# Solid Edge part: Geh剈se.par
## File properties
Username: bmolnar
Dokumentum tartalom típus: 0
Author: bmolnar
Last saved by: bmolnar
Revision: 85
Sűrűség: 0,000 kg/m^3
Pontosság: 0,990
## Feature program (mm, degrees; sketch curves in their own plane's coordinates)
base feature "unnamed BaseFeature 1"
sketch for "unnamed Protrusion 1" plane through (-60, 17.5607, 34.5) normal (-1, 0, 0) x-axis (0, 0, 1)
  circle centre (178.5, 0.4393) radius 5
extrude "unnamed Protrusion 1" add finite 0.6 along +normal
chamfer "Letörés_1" setback 0.5  SetBackValue2 = 45 deg
sketch for "Kivágás_1" plane through (-60.6, 18, 35.2406) normal (-1, 0, 0) x-axis (0, 0, 1)
  line (174.8726, 0) -> (176.316, -2.5)
  line (176.316, -2.5) -> (179.2028, -2.5)
  line (179.2028, -2.5) -> (180.6461, 0)
  line (180.6461, 0) -> (179.2028, 2.5)
  line (179.2028, 2.5) -> (176.316, 2.5)
  line (176.316, 2.5) -> (174.8726, 0)
extrude "Kivágás_1" cut finite 4 along -normal
sketch for "Furat_1" plane through (-35.4, 27, 34.5) normal (0, 1, 0) x-axis (0, 0, 1)
  hole centre (-19.5, -4.1) bore radius 4.283
hole "Furat_1" nominal diameter 9.728 finite  ThreadDepth = 6 mm; StartChamferOffset = 0.7 mm; StartChamferAngle = 45 deg
sketch for "unnamed Hole 1" plane through (-35.4, 27, 34.5) normal (0, 1, 0) x-axis (0, 0, 1)
  hole centre (197.5, -4.1) bore radius 4.283
hole "unnamed Hole 1" finite
sketch for "Furat_3" plane through (-35.4, 27, 34.5) normal (0, 1, 0) x-axis (0, 0, 1)
  hole centre (-12.5, 10.4) bore radius 3.25
hole "Furat_3" diameter 6.5 finite  CounterBoreDepth = 7.5 mm
sketch for "unnamed Hole 2" plane through (-35.4, 27, 34.5) normal (0, 1, 0) x-axis (0, 0, 1)
  hole centre (111.5, 10.4) bore radius 3.25
hole "unnamed Hole 2" finite
sketch for "unnamed Hole 3" plane through (-35.4, 27, 34.5) normal (0, 1, 0) x-axis (0, 0, 1)
  hole centre (111.5, 60.4) bore radius 3.25
hole "unnamed Hole 3" finite
sketch for "unnamed Hole 4" plane through (-35.4, 27, 34.5) normal (0, 1, 0) x-axis (0, 0, 1)
  hole centre (-12.5, 60.4) bore radius 3.25
hole "unnamed Hole 4" finite
sketch for "Furat_7" plane through (25, -11, 22) normal (0, 1, 0) x-axis (0, 0, 1)
  hole centre (0, 0) bore radius 3.3235
hole "Furat_7" nominal diameter 8 finite  ThreadDepth = 16 mm
sketch for "unnamed Hole 5" plane through (25, -11, 22) normal (0, 1, 0) x-axis (0, 0, 1)
  hole centre (124, 0) bore radius 3.3235
hole "unnamed Hole 5" finite
sketch for "unnamed Hole 6" plane through (25, -11, 22) normal (0, 1, 0) x-axis (0, 0, 1)
  hole centre (124, -50) bore radius 3.3235
hole "unnamed Hole 6" finite
sketch for "unnamed Hole 7" plane through (25, -11, 22) normal (0, 1, 0) x-axis (0, 0, 1)
  hole centre (0, -50) bore radius 3.3235
hole "unnamed Hole 7" finite
sketch for "Furat_11" plane through (22.025, -27, 34.5) normal (0, -1, 0) x-axis (0, 0, 1)
  hole centre (49.5, -2.975) bore radius 2
hole "Furat_11" diameter 4 finite  CounterBoreDepth = 3 mm; VBottomAngle = 118 deg
sketch for "Furat_12" plane through (-22.025, -27, 34.5) normal (0, -1, 0) x-axis (0, 0, 1)
  hole centre (49.5, 2.975) bore radius 2
hole "Furat_12" diameter 4 finite  VBottomAngle = 118 deg
sketch for "Furat_13" plane through (0, 0, 244) normal (0, 0, 1) x-axis (-1, 0, 0)
  hole centre (-53, -20) bore radius 3.3235
hole "Furat_13" nominal diameter 8 finite  VBottomAngle = 118 deg; ThreadDepth = 16 mm; StartChamferOffset = 0.7 mm; StartChamferAngle = 45 deg
sketch for "unnamed Hole 8" plane through (0, 0, 244) normal (0, 0, 1) x-axis (-1, 0, 0)
  hole centre (-53, 20) bore radius 3.3235
hole "unnamed Hole 8" finite
sketch for "unnamed Hole 9" plane through (0, 0, 244) normal (0, 0, 1) x-axis (-1, 0, 0)
  hole centre (53, 19) bore radius 3.3235
hole "unnamed Hole 9" finite
sketch for "unnamed Hole 10" plane through (0, 0, 244) normal (0, 0, 1) x-axis (-1, 0, 0)
  hole centre (53, -20) bore radius 3.3235
hole "unnamed Hole 10" finite
pattern "unnamed Pattern 1" of "Furat_13", "unnamed Hole 8", "unnamed Hole 9", "unnamed Hole 10"
sketch for "Furat_19" plane through (0, 0, 244) normal (0, 0, 1) x-axis (1, 0, 0)
  hole centre (25, 0) bore radius 2
hole "Furat_19" diameter 4 finite  CounterBoreDepth = 3 mm; VBottomAngle = 118 deg
sketch for "Furat_20" plane through (0, 0, 244) normal (0, 0, 1) x-axis (1, 0, 0)
  hole centre (-25, 0) bore radius 2
hole "Furat_20" diameter 4 finite  VBottomAngle = 118 deg
sketch for "Furat_21" plane through (0, 0, 13.26) normal (0, 0, -1) x-axis (0, 1, 0)
  hole centre (0, 0) bore radius 20
hole "Furat_21" diameter 40 finite
chamfer "Letörés_2" setback 0.7  SetBackValue2 = 45 deg
pattern "unnamed Pattern 2" of "Furat_1", "unnamed Hole 1"
pattern "unnamed Pattern 3" of "Furat_3", "unnamed Hole 2", "unnamed Hole 3", "unnamed Hole 4"
pattern "unnamed Pattern 4" of "Furat_7", "unnamed Hole 5", "unnamed Hole 6", "unnamed Hole 7"
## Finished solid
Body 1: solid body, 309 faces, 653 edges, 342 vertices, 1 internal void.
  Faces by surface: plane 143, cylinder 122, cone 41, torus 3
  Edges by curve: line 370, circle 279, intersection 4
Bounding box of the edges (mm; curved faces can reach further): 120.600 x 54.000 x 244.000, from (-60.6, -27, 0) to (60, 27, 244).
Cylindrical faces by radius (mm): R0.2 x31, R0.3 x1, R0.4 x8, R1.25 x4, R1.5 x12, R2 x4, R2.25 x2, R2.5 x8, R3.25 x4, R3.3235 x12, R4.283 x2, R5 x2, R5.5 x4, R6 x1, R6.36 x1, R6.85 x1, R8 x2, R8.25 x2, R10.5 x2, R12.6 x2, R13 x1, R14 x4, R17 x2, R19.175 x2, R20 x1, R20.95 x1, R21 x4, R22.25 x2
Conical faces (half-angle, radius in mm at the cone's reference point): 7 deg R7.6825 x1, 14 deg R6.225 x1, 14 deg R6.5711 x1, 17 deg R6.225 x1, 23 deg R6.919 x1, 30 deg R6.1443 x1, 30 deg R10.45 x2, 30 deg R11.6624 x2, 42.5 deg R6.2133 x1, 45 deg R4.0235 x8, 45 deg R4.75 x1, 45 deg R4.983 x2, 45 deg R5 x1, 45 deg R14.15 x2, 45 deg R20.5 x1, 45 deg R21.25 x2, 59 deg R2 x4, 59 deg R3.3235 x4, 60 deg R10.5196 x2, 84 deg R6.5508 x1, 85 deg R8.0363 x1, 87 deg R6.2665 x1
Toroidal faces (ring radius, tube radius in mm): R6.8957 r0.2025 x1, R7.3422 r0.2925 x1, R8.05 r0.2 x1
Planar faces by outward normal: +x 16, +y 23, +z 13, -x 20, -y 26, -z 17, oblique 28
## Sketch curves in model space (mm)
circle centre (-60.6, 18, 213) radius 2.5
line (-60.6, 18, 215.8868) -> (-60.6, 20.5, 214.4434)
line (-60.6, 20.5, 214.4434) -> (-60.6, 20.5, 211.5566)
line (-60.6, 20.5, 211.5566) -> (-60.6, 18, 210.1132)
line (-60.6, 18, 210.1132) -> (-60.6, 15.5, 211.5566)
line (-60.6, 15.5, 211.5566) -> (-60.6, 15.5, 214.4434)
line (-60.6, 15.5, 214.4434) -> (-60.6, 18, 215.8868)
circle centre (-60, 18, 213) radius 5
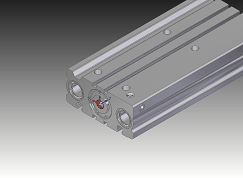
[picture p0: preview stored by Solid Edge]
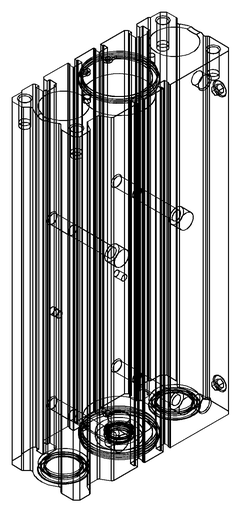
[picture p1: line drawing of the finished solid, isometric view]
